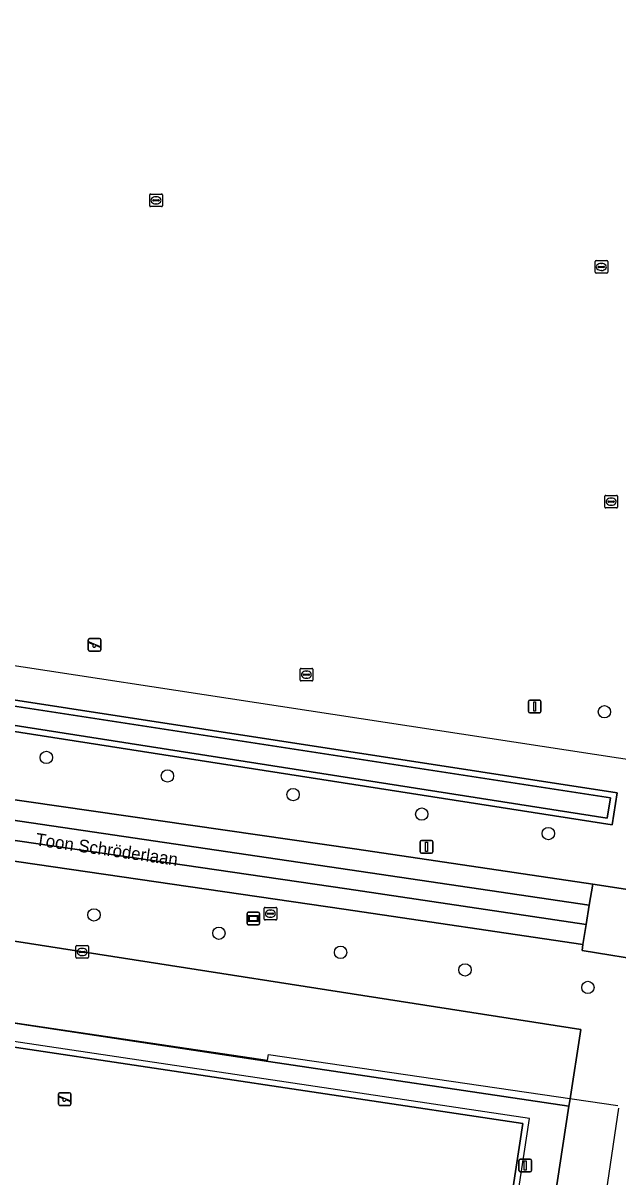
# Model space of a CAD drawing. Extents: x 161090 to 161692, y 379509 to 380907.
# Drawn here: x 161507.3 to 161554.5, y 380121.1 to 380212.6 of the extents above; entities that cross this region are included whole.
import ezdxf

# ---------------------------------------------------------------- set-up
doc = ezdxf.new("R2010")
doc.units = 0
for name, color, linetype in [('IMGEO_Boom', 7, 'Continuous'), ('IMGEO_Brandkraan', 7, 'Continuous'), ('IMGEO_Greppel_droge_sloot', 7, 'Continuous'), ('IMGEO_Groenvoorziening', 7, 'Continuous'), ('IMGEO_Hek', 7, 'Continuous'), ('IMGEO_Lichtmast', 7, 'Continuous'), ('IMGEO_Oever', 7, 'Continuous'), ('IMGEO_Openbare_ruimte_label', 7, 'Continuous'), ('IMGEO_Rijbaan_lokaal_gesloten', 7, 'Continuous'), ('IMGEO_Rijbaan_lokaal_open', 7, 'Continuous'), ('IMGEO_Rioolput', 7, 'Continuous'), ('IMGEO_Speelvoorziening', 7, 'Continuous'), ('IMGEO_Terreindeel_open', 7, 'Continuous'), ('IMGEO_Verklikker', 7, 'Continuous'), ('IMGEO_Voetpad_open', 7, 'Continuous'), ('IMGEO_Waterleidingput', 7, 'Continuous')]:
    doc.layers.add(name, color=color, linetype=linetype)

msp = doc.modelspace()

# ---------------------------------------------------------------- linework, layer by layer
at = {"layer": 'IMGEO_Boom'}
for centre in [(161553.395, 380158.024), (161509.163, 380154.409), (161518.76, 380152.937), (161528.716, 380151.457), (161538.917, 380149.914), (161548.952, 380148.375), (161512.94, 380141.927), (161522.845, 380140.47), (161532.489, 380138.953), (161542.348, 380137.559), (161552.088, 380136.168)]:
    msp.add_circle(centre, 0.489, dxfattribs=at)
at = {"layer": 'IMGEO_Brandkraan'}
for p, q in [((161526.422, 380141.592), (161526.422, 380142.444)), ((161526.497, 380142.518), (161527.349, 380142.518)), ((161526.91, 380142.298), (161526.935, 380142.298)), ((161527.423, 380142.444), (161527.423, 380141.592)), ((161527.349, 380141.518), (161526.497, 380141.518)), ((161526.681, 380142.012), (161526.681, 380142.024)), ((161527.119, 380141.975), (161526.721, 380141.975)), ((161526.724, 380142.061), (161527.122, 380142.061)), ((161526.933, 380141.738), (161526.908, 380141.738)), ((161527.165, 380142.024), (161527.165, 380142.012))]:
    msp.add_line(p, q, dxfattribs=at)
for points in [[(161526.422, 380141.592), (161526.422, 380142.444)], [(161526.497, 380142.518), (161527.349, 380142.518)], [(161527.423, 380142.444), (161527.423, 380141.592)], [(161527.349, 380141.518), (161526.497, 380141.518)]]:
    msp.add_lwpolyline(points, dxfattribs=at)
for centre, radius, start, end in [((161526.499, 380142.442), 0.0765, 91.55205, 178.44795), ((161526.499, 380142.442), 0.0765, 91.55205, 178.44795), ((161527.347, 380142.442), 0.0765, 1.55205, 88.44795), ((161527.347, 380142.442), 0.0765, 1.55205, 88.44795), ((161526.499, 380141.594), 0.0765, 181.55205, 268.44795), ((161526.499, 380141.594), 0.0765, 181.55205, 268.44795), ((161526.721, 380142.021), 0.0403, 85.87752, 175.75265), ((161526.718, 380142.011), 0.0366, 178.93798, 274.71019), ((161527.122, 380142.018), 0.043, 264.86636, 352.45326), ((161527.126, 380142.023), 0.0386, 1.73085, 96.63898), ((161527.347, 380141.594), 0.0765, 271.55205, 358.44795), ((161527.347, 380141.594), 0.0765, 271.55205, 358.44795)]:
    msp.add_arc(centre, radius, start, end, dxfattribs=at)
for centre, major_axis, ratio, start_param, end_param in [((161526.909, 380142.018), (-0.387, 0.002), 0.722429, 4.712389, 7.853982), ((161526.934, 380142.018), (-0.39, 0.002), 0.717154, 1.570796, 4.712389)]:
    msp.add_ellipse(centre, major_axis=major_axis, ratio=ratio, start_param=start_param, end_param=end_param, dxfattribs=at)
at = {"layer": 'IMGEO_Greppel_droge_sloot'}
msp.add_lwpolyline([(161473.065, 380163.338), (161472.907, 380162.528), (161473.828, 380162.362), (161500.075, 380157.97), (161553.617, 380149.602), (161553.869, 380151.216), (161499.931, 380159.506)], close=True, dxfattribs=at)
at = {"layer": 'IMGEO_Groenvoorziening'}
for points in [[(161500, 380159.97), (161554.405, 380151.608), (161554.008, 380149.066), (161500, 380157.507)], [(161558.658, 380111.326), (161562.431, 380135.511), (161562.682, 380137.292), (161551.641, 380139.098), (161551.698, 380139.577), (161532.737, 380142.374), (161504.241, 380146.538), (161486.012, 380149.348), (161471.762, 380151.473), (161470.795, 380145.44), (161500, 380140.879), (161551.533, 380132.833), (161550.65, 380127.178), (161550.583, 380126.751), (161533.851, 380017.034)], [(161505.002, 380151.276), (161533.779, 380147.123), (161552.468, 380144.356), (161563.514, 380142.679)]]:
    msp.add_lwpolyline(points, dxfattribs=at)
msp.add_lwpolyline([(161470.795, 380145.44), (161469.909, 380139.909), (161469.816, 380139.327), (161470.844, 380139.17), (161471.241, 380139.11), (161471.178, 380138.695), (161476.394, 380137.909), (161500.889, 380134.218), (161526.76, 380130.285), (161550.583, 380126.751), (161550.65, 380127.178), (161551.533, 380132.833), (161500, 380140.879)], close=True, dxfattribs=at)
at = {"layer": 'IMGEO_Hek'}
for points in [[(161558.655, 380153.718), (161472.202, 380166.92), (161467.427, 380173.551), (161469.43, 380186.379), (161475.815, 380227.062), (161478.929, 380247.203)], [(161469.666, 380139.945), (161469.909, 380139.909), (161470.935, 380139.757), (161470.838, 380139.11), (161501.266, 380134.593), (161501.176, 380134.189), (161526.703, 380130.395), (161526.77, 380130.85), (161554.448, 380126.797)], [(161459.798, 380029.532), (161531.163, 380018.876), (161534.934, 380043.376), (161537.395, 380042.998), (161538.44, 380050.25), (161535.99, 380050.634), (161542.6, 380093.986), (161545.043, 380093.588), (161546.157, 380100.79), (161543.702, 380101.148), (161547.462, 380125.77), (161476.115, 380136.431), (161472.333, 380111.821), (161469.879, 380112.192), (161468.777, 380104.974), (161471.226, 380104.631), (161470.057, 380096.97)], [(161554.512, 380126.608), (161529.782, 379959.399)]]:
    msp.add_lwpolyline(points, dxfattribs=at)
at = {"layer": 'IMGEO_Lichtmast'}
for p, q in [((161547.377, 380158.04), (161547.377, 380158.84)), ((161547.377, 380158.84), (161547.377, 380158.04)), ((161547.477, 380158.94), (161548.267, 380158.94)), ((161548.267, 380158.94), (161547.477, 380158.94)), ((161548.367, 380158.84), (161548.367, 380158.04)), ((161548.367, 380158.04), (161548.367, 380158.84)), ((161548.267, 380157.94), (161547.477, 380157.94)), ((161547.477, 380157.94), (161548.267, 380157.94)), ((161538.801, 380146.92), (161538.801, 380147.72)), ((161538.801, 380147.72), (161538.801, 380146.92)), ((161538.901, 380147.82), (161539.691, 380147.82)), ((161539.691, 380147.82), (161538.901, 380147.82)), ((161539.791, 380147.72), (161539.791, 380146.92)), ((161539.791, 380146.92), (161539.791, 380147.72)), ((161539.691, 380146.82), (161538.901, 380146.82)), ((161538.901, 380146.82), (161539.691, 380146.82)), ((161546.625, 380121.656), (161546.625, 380122.456)), ((161546.625, 380122.456), (161546.625, 380121.656)), ((161546.725, 380122.556), (161547.515, 380122.556)), ((161547.515, 380122.556), (161546.725, 380122.556)), ((161547.615, 380122.456), (161547.615, 380121.656)), ((161547.615, 380121.656), (161547.615, 380122.456)), ((161547.515, 380121.556), (161546.725, 380121.556)), ((161546.725, 380121.556), (161547.515, 380121.556))]:
    msp.add_line(p, q, dxfattribs=at)
for points in [[(161547.797, 380158.815), (161547.947, 380158.815), (161547.947, 380158.065), (161547.797, 380158.065), (161547.797, 380158.815)], [(161539.221, 380147.695), (161539.371, 380147.695), (161539.371, 380146.945), (161539.221, 380146.945), (161539.221, 380147.695)], [(161547.045, 380122.431), (161547.195, 380122.431), (161547.195, 380121.681), (161547.045, 380121.681), (161547.045, 380122.431)]]:
    msp.add_lwpolyline(points, dxfattribs=at)
for centre, start, end in [((161547.477, 380158.84), 90, 180), ((161547.477, 380158.84), 90, 180), ((161548.267, 380158.84), 0, 90), ((161548.267, 380158.84), 360, 90), ((161547.477, 380158.04), 180, 270), ((161547.477, 380158.04), 180, 270), ((161548.267, 380158.04), 270, 0), ((161548.267, 380158.04), 270, 0), ((161538.901, 380147.72), 90, 180), ((161538.901, 380147.72), 90, 180), ((161539.691, 380147.72), 0, 90), ((161539.691, 380147.72), 360, 90), ((161538.901, 380146.92), 180, 270), ((161538.901, 380146.92), 180, 270), ((161539.691, 380146.92), 270, 0), ((161539.691, 380146.92), 270, 0), ((161546.725, 380122.456), 90, 180), ((161546.725, 380122.456), 90, 180), ((161547.515, 380122.456), 0, 90), ((161547.515, 380122.456), 360, 90), ((161546.725, 380121.656), 180, 270), ((161546.725, 380121.656), 180, 270), ((161547.515, 380121.656), 270, 0), ((161547.515, 380121.656), 270, 0)]:
    msp.add_arc(centre, 0.1, start, end, dxfattribs=at)
at = {"layer": 'IMGEO_Oever'}
for points in [[(161500, 380159.97), (161472.69, 380163.865), (161472.356, 380162.15), (161473.748, 380161.9), (161500, 380157.507), (161554.008, 380149.066), (161554.405, 380151.608)], [(161473.065, 380163.338), (161499.931, 380159.506), (161553.869, 380151.216), (161553.617, 380149.602), (161500.075, 380157.97), (161473.828, 380162.362), (161472.907, 380162.528)]]:
    msp.add_lwpolyline(points, close=True, dxfattribs=at)
at = {"layer": 'IMGEO_Rijbaan_lokaal_gesloten'}
for points in [[(161504.718, 380149.687), (161533.226, 380145.488), (161552.181, 380142.696), (161552.468, 380144.356), (161533.779, 380147.123), (161505.002, 380151.276)], [(161504.241, 380146.538), (161532.737, 380142.374), (161551.698, 380139.577), (161551.948, 380141.154), (161532.99, 380143.989), (161504.507, 380148.144)]]:
    msp.add_lwpolyline(points, dxfattribs=at)
at = {"layer": 'IMGEO_Rijbaan_lokaal_open'}
for points in [[(161464.235, 380155.875), (161464.019, 380154.384), (161471.474, 380153.186), (161486.372, 380150.902), (161504.507, 380148.144), (161532.99, 380143.989), (161551.948, 380141.154), (161552.181, 380142.696), (161533.226, 380145.488), (161504.718, 380149.687), (161486.778, 380152.4), (161471.842, 380154.694)], [(161563.514, 380142.679), (161552.468, 380144.356), (161552.181, 380142.696), (161551.948, 380141.154), (161551.698, 380139.577), (161551.641, 380139.098), (161562.682, 380137.292)]]:
    msp.add_lwpolyline(points, close=True, dxfattribs=at)
at = {"layer": 'IMGEO_Rioolput'}
for p, q in [((161511.495, 380138.559), (161511.495, 380139.411)), ((161511.57, 380139.485), (161512.422, 380139.485)), ((161512.496, 380139.411), (161512.496, 380138.559)), ((161512.422, 380138.485), (161511.57, 380138.485)), ((161511.754, 380138.979), (161511.754, 380138.991)), ((161512.192, 380138.942), (161511.794, 380138.942)), ((161511.797, 380139.028), (161512.195, 380139.028)), ((161512.006, 380138.705), (161511.981, 380138.705)), ((161511.983, 380139.265), (161512.008, 380139.265)), ((161512.238, 380138.991), (161512.238, 380138.979))]:
    msp.add_line(p, q, dxfattribs=at)
for points in [[(161511.495, 380138.559), (161511.495, 380139.411)], [(161511.57, 380139.485), (161512.422, 380139.485)], [(161512.496, 380139.411), (161512.496, 380138.559)], [(161512.422, 380138.485), (161511.57, 380138.485)]]:
    msp.add_lwpolyline(points, dxfattribs=at)
for centre, radius, start, end in [((161511.572, 380139.409), 0.0765, 91.55205, 178.44795), ((161511.572, 380139.409), 0.0765, 91.55205, 178.44795), ((161512.42, 380139.409), 0.0765, 1.55205, 88.44795), ((161512.42, 380139.409), 0.0765, 1.55205, 88.44795), ((161511.572, 380138.561), 0.0765, 181.55205, 268.44795), ((161511.572, 380138.561), 0.0765, 181.55205, 268.44795), ((161511.794, 380138.988), 0.0403, 85.87752, 175.75265), ((161511.791, 380138.978), 0.0366, 178.93798, 274.71019), ((161512.195, 380138.985), 0.043, 264.86636, 352.45326), ((161512.199, 380138.99), 0.0386, 1.73085, 96.63898), ((161512.42, 380138.561), 0.0765, 271.55205, 358.44795), ((161512.42, 380138.561), 0.0765, 271.55205, 358.44795)]:
    msp.add_arc(centre, radius, start, end, dxfattribs=at)
for centre, major_axis, ratio, start_param, end_param in [((161511.982, 380138.985), (-0.387, 0.002), 0.722429, 4.712389, 7.853982), ((161512.007, 380138.985), (-0.39, 0.002), 0.717154, 1.570796, 4.712389)]:
    msp.add_ellipse(centre, major_axis=major_axis, ratio=ratio, start_param=start_param, end_param=end_param, dxfattribs=at)
at = {"layer": 'IMGEO_Speelvoorziening'}
for p, q in [((161512.491, 380162.937), (161512.491, 380163.737)), ((161512.491, 380163.737), (161512.491, 380162.937)), ((161512.874, 380163.365), (161512.535, 380163.502)), ((161512.56, 380163.562), (161513.436, 380163.209)), ((161512.591, 380163.837), (161513.381, 380163.837)), ((161513.381, 380163.837), (161512.591, 380163.837)), ((161513.412, 380163.149), (161513.072, 380163.286)), ((161513.481, 380163.737), (161513.481, 380162.937)), ((161513.481, 380162.937), (161513.481, 380163.737)), ((161513.381, 380162.837), (161512.591, 380162.837)), ((161512.591, 380162.837), (161513.381, 380162.837)), ((161510.115, 380126.922), (161510.115, 380127.722)), ((161510.115, 380127.722), (161510.115, 380126.922)), ((161510.498, 380127.35), (161510.159, 380127.487)), ((161510.184, 380127.547), (161511.06, 380127.194)), ((161510.215, 380127.822), (161511.005, 380127.822)), ((161511.005, 380127.822), (161510.215, 380127.822)), ((161511.105, 380127.722), (161511.105, 380126.922)), ((161511.105, 380126.922), (161511.105, 380127.722)), ((161511.005, 380126.822), (161510.215, 380126.822)), ((161510.215, 380126.822), (161511.005, 380126.822)), ((161511.036, 380127.134), (161510.696, 380127.271))]:
    msp.add_line(p, q, dxfattribs=at)
for centre, radius, start, end in [((161512.591, 380163.737), 0.1, 90, 180), ((161512.591, 380163.737), 0.1, 90, 180), ((161512.548, 380163.532), 0.0327, 68.07798, 248.07798), ((161512.953, 380163.275), 0.12, 130.99278, 5.16318), ((161513.381, 380163.737), 0.1, 0, 90), ((161513.381, 380163.737), 0.1, 360, 90), ((161513.424, 380163.179), 0.0327, 248.07798, 68.07798), ((161512.591, 380162.937), 0.1, 180, 270), ((161512.591, 380162.937), 0.1, 180, 270), ((161513.381, 380162.937), 0.1, 270, 0), ((161513.381, 380162.937), 0.1, 270, 0), ((161510.215, 380127.722), 0.1, 90, 180), ((161510.215, 380127.722), 0.1, 90, 180), ((161510.172, 380127.517), 0.0327, 68.07798, 248.07798), ((161511.005, 380127.722), 0.1, 0, 90), ((161511.005, 380127.722), 0.1, 360, 90), ((161510.215, 380126.922), 0.1, 180, 270), ((161510.215, 380126.922), 0.1, 180, 270), ((161510.577, 380127.26), 0.12, 130.99278, 5.16318), ((161511.005, 380126.922), 0.1, 270, 0), ((161511.005, 380126.922), 0.1, 270, 0), ((161511.048, 380127.164), 0.0327, 248.07798, 68.07798)]:
    msp.add_arc(centre, radius, start, end, dxfattribs=at)
at = {"layer": 'IMGEO_Terreindeel_open'}
msp.add_lwpolyline([(161546.934, 380125.374), (161476.501, 380135.966), (161460.682, 380032.191), (161460.459, 380030.026), (161530.75, 380019.421)], close=True, dxfattribs=at)
at = {"layer": 'IMGEO_Verklikker'}
for p, q in [((161525.169, 380142.136), (161525.959, 380142.136)), ((161525.959, 380142.136), (161525.169, 380142.136)), ((161525.069, 380141.236), (161525.069, 380142.036)), ((161525.069, 380142.036), (161525.069, 380141.236)), ((161526.059, 380142.036), (161526.059, 380141.236)), ((161526.059, 380141.236), (161526.059, 380142.036)), ((161525.959, 380141.136), (161525.169, 380141.136)), ((161525.169, 380141.136), (161525.959, 380141.136))]:
    msp.add_line(p, q, dxfattribs=at)
for points in [[(161525.17, 380141.868), (161525.958, 380141.868), (161525.958, 380141.404), (161525.17, 380141.404), (161525.17, 380141.868)], [(161525.235, 380141.803), (161525.235, 380141.469), (161525.893, 380141.469), (161525.893, 380141.803), (161525.235, 380141.803)]]:
    msp.add_lwpolyline(points, dxfattribs=at)
for centre, start, end in [((161525.169, 380142.036), 90, 180), ((161525.169, 380142.036), 90, 180), ((161525.959, 380142.036), 0, 90), ((161525.959, 380142.036), 360, 90), ((161525.169, 380141.236), 180, 270), ((161525.169, 380141.236), 180, 270), ((161525.959, 380141.236), 270, 0), ((161525.959, 380141.236), 270, 0)]:
    msp.add_arc(centre, 0.1, start, end, dxfattribs=at)
at = {"layer": 'IMGEO_Voetpad_open'}
msp.add_lwpolyline([(161533.851, 380017.034), (161550.583, 380126.751), (161526.76, 380130.285), (161500.889, 380134.218), (161476.394, 380137.909), (161471.178, 380138.695), (161471.079, 380138.046), (161462.527, 380081.755)], dxfattribs=at)
msp.add_lwpolyline([(161476.501, 380135.966), (161546.934, 380125.374), (161530.75, 380019.421), (161460.459, 380030.026), (161460.682, 380032.191)], close=True, dxfattribs=at)
at = {"layer": 'IMGEO_Waterleidingput'}
for p, q in [((161517.356, 380198.156), (161517.356, 380199.008)), ((161517.431, 380199.082), (161518.283, 380199.082)), ((161517.844, 380198.862), (161517.869, 380198.862)), ((161518.357, 380199.008), (161518.357, 380198.156)), ((161518.283, 380198.082), (161517.431, 380198.082)), ((161517.615, 380198.576), (161517.615, 380198.588)), ((161518.053, 380198.539), (161517.655, 380198.539)), ((161517.658, 380198.625), (161518.056, 380198.625)), ((161517.867, 380198.302), (161517.842, 380198.302)), ((161518.099, 380198.588), (161518.099, 380198.576)), ((161552.655, 380192.874), (161552.655, 380193.726)), ((161552.73, 380193.8), (161553.582, 380193.8)), ((161552.957, 380193.343), (161553.355, 380193.343)), ((161553.143, 380193.58), (161553.168, 380193.58)), ((161553.656, 380193.726), (161553.656, 380192.874)), ((161553.582, 380192.8), (161552.73, 380192.8)), ((161552.914, 380193.294), (161552.914, 380193.306)), ((161553.352, 380193.257), (161552.954, 380193.257)), ((161553.166, 380193.02), (161553.141, 380193.02)), ((161553.398, 380193.306), (161553.398, 380193.294)), ((161553.426, 380174.263), (161553.426, 380175.115)), ((161553.501, 380175.189), (161554.353, 380175.189)), ((161554.427, 380175.115), (161554.427, 380174.263)), ((161554.353, 380174.189), (161553.501, 380174.189)), ((161553.685, 380174.683), (161553.685, 380174.695)), ((161554.123, 380174.646), (161553.725, 380174.646)), ((161553.728, 380174.732), (161554.126, 380174.732)), ((161553.937, 380174.409), (161553.912, 380174.409)), ((161553.914, 380174.969), (161553.939, 380174.969)), ((161554.169, 380174.695), (161554.169, 380174.683)), ((161529.277, 380160.544), (161529.277, 380161.396)), ((161529.352, 380161.47), (161530.204, 380161.47)), ((161530.278, 380161.396), (161530.278, 380160.544)), ((161530.204, 380160.47), (161529.352, 380160.47)), ((161529.536, 380160.964), (161529.536, 380160.976)), ((161529.974, 380160.927), (161529.576, 380160.927)), ((161529.579, 380161.013), (161529.977, 380161.013)), ((161529.788, 380160.69), (161529.763, 380160.69)), ((161529.765, 380161.25), (161529.79, 380161.25)), ((161530.02, 380160.976), (161530.02, 380160.964))]:
    msp.add_line(p, q, dxfattribs=at)
for points in [[(161517.356, 380198.156), (161517.356, 380199.008)], [(161517.431, 380199.082), (161518.283, 380199.082)], [(161518.357, 380199.008), (161518.357, 380198.156)], [(161518.283, 380198.082), (161517.431, 380198.082)], [(161552.655, 380192.874), (161552.655, 380193.726)], [(161552.73, 380193.8), (161553.582, 380193.8)], [(161553.656, 380193.726), (161553.656, 380192.874)], [(161553.582, 380192.8), (161552.73, 380192.8)], [(161553.426, 380174.263), (161553.426, 380175.115)], [(161553.501, 380175.189), (161554.353, 380175.189)], [(161554.427, 380175.115), (161554.427, 380174.263)], [(161554.353, 380174.189), (161553.501, 380174.189)], [(161529.277, 380160.544), (161529.277, 380161.396)], [(161529.352, 380161.47), (161530.204, 380161.47)], [(161530.278, 380161.396), (161530.278, 380160.544)], [(161530.204, 380160.47), (161529.352, 380160.47)]]:
    msp.add_lwpolyline(points, dxfattribs=at)
for centre, radius, start, end in [((161517.433, 380199.006), 0.0765, 91.55205, 178.44795), ((161517.433, 380199.006), 0.0765, 91.55205, 178.44795), ((161518.281, 380199.006), 0.0765, 1.55205, 88.44795), ((161518.281, 380199.006), 0.0765, 1.55205, 88.44795), ((161517.433, 380198.158), 0.0765, 181.55205, 268.44795), ((161517.433, 380198.158), 0.0765, 181.55205, 268.44795), ((161517.655, 380198.585), 0.0403, 85.87752, 175.75265), ((161517.652, 380198.575), 0.0366, 178.93798, 274.71019), ((161518.056, 380198.582), 0.043, 264.86636, 352.45326), ((161518.06, 380198.587), 0.0386, 1.73085, 96.63898), ((161518.281, 380198.158), 0.0765, 271.55205, 358.44795), ((161518.281, 380198.158), 0.0765, 271.55205, 358.44795), ((161552.732, 380193.724), 0.0765, 91.55205, 178.44795), ((161552.732, 380193.724), 0.0765, 91.55205, 178.44795), ((161552.954, 380193.303), 0.0403, 85.87752, 175.75265), ((161553.359, 380193.305), 0.0386, 1.73085, 96.63898), ((161553.58, 380193.724), 0.0765, 1.55205, 88.44795), ((161553.58, 380193.724), 0.0765, 1.55205, 88.44795), ((161552.732, 380192.876), 0.0765, 181.55205, 268.44795), ((161552.732, 380192.876), 0.0765, 181.55205, 268.44795), ((161552.951, 380193.293), 0.0366, 178.93798, 274.71019), ((161553.355, 380193.3), 0.043, 264.86636, 352.45326), ((161553.58, 380192.876), 0.0765, 271.55205, 358.44795), ((161553.58, 380192.876), 0.0765, 271.55205, 358.44795), ((161553.503, 380175.113), 0.0765, 91.55205, 178.44795), ((161553.503, 380175.113), 0.0765, 91.55205, 178.44795), ((161554.351, 380175.113), 0.0765, 1.55205, 88.44795), ((161554.351, 380175.113), 0.0765, 1.55205, 88.44795), ((161553.503, 380174.265), 0.0765, 181.55205, 268.44795), ((161553.503, 380174.265), 0.0765, 181.55205, 268.44795), ((161553.725, 380174.692), 0.0403, 85.87752, 175.75265), ((161553.722, 380174.682), 0.0366, 178.93798, 274.71019), ((161554.126, 380174.689), 0.043, 264.86636, 352.45326), ((161554.13, 380174.694), 0.0386, 1.73085, 96.63898), ((161554.351, 380174.265), 0.0765, 271.55205, 358.44795), ((161554.351, 380174.265), 0.0765, 271.55205, 358.44795), ((161529.354, 380161.394), 0.0765, 91.55205, 178.44795), ((161529.354, 380161.394), 0.0765, 91.55205, 178.44795), ((161530.202, 380161.394), 0.0765, 1.55205, 88.44795), ((161530.202, 380161.394), 0.0765, 1.55205, 88.44795), ((161529.354, 380160.546), 0.0765, 181.55205, 268.44795), ((161529.354, 380160.546), 0.0765, 181.55205, 268.44795), ((161529.576, 380160.973), 0.0403, 85.87752, 175.75265), ((161529.573, 380160.963), 0.0366, 178.93798, 274.71019), ((161529.977, 380160.97), 0.043, 264.86636, 352.45326), ((161529.981, 380160.975), 0.0386, 1.73085, 96.63898), ((161530.202, 380160.546), 0.0765, 271.55205, 358.44795), ((161530.202, 380160.546), 0.0765, 271.55205, 358.44795)]:
    msp.add_arc(centre, radius, start, end, dxfattribs=at)
for centre, major_axis, ratio, start_param, end_param in [((161517.843, 380198.582), (-0.387, 0.002), 0.722429, 4.712389, 7.853982), ((161517.868, 380198.582), (-0.39, 0.002), 0.717154, 1.570796, 4.712389), ((161553.142, 380193.3), (-0.387, 0.002), 0.722429, 4.712389, 7.853982), ((161553.167, 380193.3), (-0.39, 0.002), 0.717154, 1.570796, 4.712389), ((161553.913, 380174.689), (-0.387, 0.002), 0.722429, 4.712389, 7.853982), ((161553.938, 380174.689), (-0.39, 0.002), 0.717154, 1.570796, 4.712389), ((161529.764, 380160.97), (-0.387, 0.002), 0.722429, 4.712389, 7.853982), ((161529.789, 380160.97), (-0.39, 0.002), 0.717154, 1.570796, 4.712389)]:
    msp.add_ellipse(centre, major_axis=major_axis, ratio=ratio, start_param=start_param, end_param=end_param, dxfattribs=at)

# ---------------------------------------------------------------- texts
at = {"layer": 'IMGEO_Openbare_ruimte_label'}
msp.add_text('Toon Schröderlaan', height=1, rotation=351.78079, dxfattribs=at).set_placement((161508.258, 380147.434))

doc.saveas('drawing.dxf')
